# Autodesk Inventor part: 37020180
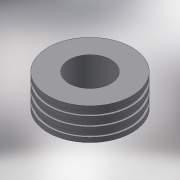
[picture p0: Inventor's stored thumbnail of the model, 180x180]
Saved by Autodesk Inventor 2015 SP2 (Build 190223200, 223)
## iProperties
Created: 2017-08
Part Number: 37020180
Material: Generic
Description: PLASSON MAN HOLE ADAPTOR 180
Document SubType Name: Modeling
Designer: Кирилл
Density: 1 g/cm^3
Appearance: Default
Author: Кирилл
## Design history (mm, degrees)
derived "37020-477207.ipt"
feature "Solid1::37020-477207.ipt"
tag "TaggingFeature1"
body "Solid1"
other parameters: "d0" = 135, "d1" = 335, "d2" = 318.25, "d3" = 157, "d6" = 66, "L_" = 135, "d_1" = 157, "D_" = 335, "H_" = 66
